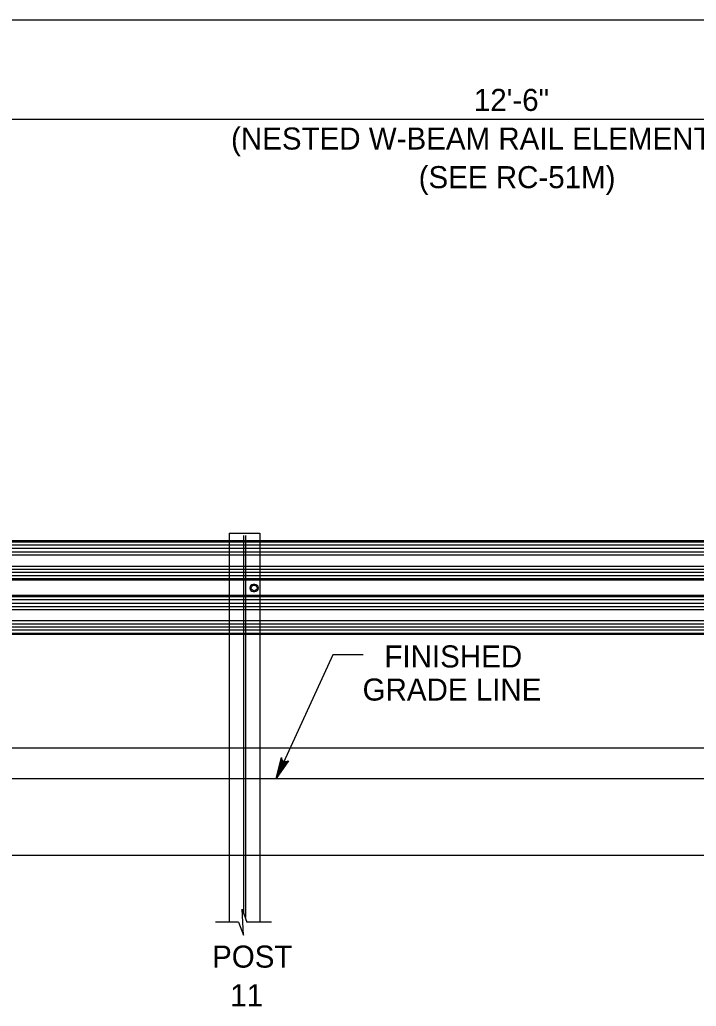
# Model space of a CAD drawing. Extents: x 632007860 to 635435983, y 295418622 to 297794622.
# Drawn here: x 632449960 to 632541897, y 296213999 to 296348078 of the extents above; entities that cross this region are included whole.
import ezdxf

# ---------------------------------------------------------------- set-up
doc = ezdxf.new("R2010")
doc.units = 0
for name, color, linetype in [('S-ABUT', 7, 'Continuous'), ('S-DETL-DIMS', 7, 'Continuous'), ('S-DETL-T120', 7, 'Continuous'), ('S-GRND-MAJR', 7, 'Continuous'), ('S-STEL', 7, 'Continuous')]:
    doc.layers.add(name, color=color, linetype=linetype)

msp = doc.modelspace()

# ---------------------------------------------------------------- linework, layer by layer
at = {"layer": 'S-ABUT'}
for p, q in [((632118834, 296249115), (632656122, 296249115)), ((632141627, 296234532), (632656122, 296234532))]:
    msp.add_line(p, q, dxfattribs=at)
at = {"layer": 'S-DETL-DIMS'}
for p, q in [((632118834, 296348078), (632598995, 296348078)), ((632130592, 296334582), (632596456, 296334582)), ((632492491, 296261755), (632484794, 296244949)), ((632496618, 296261755), (632492491, 296261755)), ((632479670, 296225427), (632476544, 296225427)), ((632484170, 296225427), (632480841, 296225427))]:
    msp.add_line(p, q, dxfattribs=at)
for points in [[(632484794, 296244949), (632485510, 296247824), (632485534, 296247690), (632485558, 296247555), (632485623, 296247462), (632485687, 296247369), (632485769, 296247313), (632485851, 296247257), (632485947, 296247231), (632486043, 296247206), (632486155, 296247218), (632486268, 296247230), (632486386, 296247300), (632486503, 296247369), (632484794, 296244949), (632486386, 296247300), (632486268, 296247230), (632484794, 296244949), (632486155, 296247218), (632486043, 296247206), (632484794, 296244949), (632485947, 296247231), (632485851, 296247257), (632484794, 296244949), (632485769, 296247313), (632485687, 296247369), (632484794, 296244949), (632485623, 296247462), (632485558, 296247555), (632484794, 296244949), (632485534, 296247690)], [(632479670, 296225427), (632480383, 296223669), (632480170, 296227184), (632480841, 296225427)]]:
    msp.add_lwpolyline(points, dxfattribs=at)
at = {"layer": 'S-GRND-MAJR'}
msp.add_line((632118834, 296244949), (632656122, 296244949), dxfattribs=at)
at = {"layer": 'S-STEL'}
for p, q in [((632647109, 296277239), (632437249, 296277239)), ((632647109, 296277070), (632437249, 296277070)), ((632478423, 296278280), (632482591, 296278280)), ((632478423, 296278280), (632478423, 296277238)), ((632478423, 296278280), (632482591, 296278280)), ((632478423, 296278280), (632478423, 296277238)), ((632478423, 296277238), (632478423, 296264508)), ((632480377, 296277997), (632480377, 296226558)), ((632480637, 296277997), (632480637, 296226047)), ((632482591, 296278280), (632482591, 296277238)), ((632482591, 296278280), (632482591, 296277238)), ((632482591, 296277238), (632482591, 296264508)), ((632647109, 296276648), (632437222, 296276648)), ((632647109, 296276648), (632437249, 296276648)), ((632647109, 296276227), (632437249, 296276227)), ((632647389, 296275721), (632437249, 296275721)), ((632647007, 296275299), (632437249, 296275299)), ((632647109, 296273782), (632437249, 296273782)), ((632647109, 296273360), (632437249, 296273360)), ((632647109, 296272939), (632437249, 296272939)), ((632647109, 296272517), (632437249, 296272517)), ((632647109, 296272096), (632437249, 296272096)), ((632647109, 296271927), (632437249, 296271927)), ((632481232, 296270862), (632481232, 296270854)), ((632481232, 296270862), (632481232, 296270854)), ((632481232, 296270845), (632481232, 296270837)), ((632481930, 296271328), (632481697, 296271328)), ((632481930, 296271328), (632481697, 296271328)), ((632481930, 296271310), (632481697, 296271310)), ((632481697, 296270389), (632481930, 296270389)), ((632481697, 296270389), (632481930, 296270389)), ((632481697, 296270371), (632481930, 296270371)), ((632482395, 296270854), (632482395, 296270862)), ((632482395, 296270854), (632482395, 296270862)), ((632482395, 296270837), (632482395, 296270845)), ((632647109, 296269819), (632437249, 296269819)), ((632647109, 296269651), (632437249, 296269651)), ((632647109, 296269229), (632437249, 296269229)), ((632647109, 296268723), (632437249, 296268723)), ((632647454, 296268302), (632437249, 296268302)), ((632647045, 296267880), (632437249, 296267880)), ((632647109, 296266363), (632437249, 296266363)), ((632647109, 296265941), (632437249, 296265941)), ((632647109, 296265520), (632437249, 296265520)), ((632647109, 296265098), (632437249, 296265098)), ((632647109, 296264677), (632437249, 296264677)), ((632647109, 296264508), (632437249, 296264508)), ((632478423, 296264508), (632478423, 296244948)), ((632482591, 296264508), (632482591, 296244948)), ((632478423, 296244948), (632478423, 296225426)), ((632482591, 296244948), (632482591, 296225426))]:
    msp.add_line(p, q, dxfattribs=at)
msp.add_circle((632481813, 296270858), 391, dxfattribs=at)
msp.add_circle((632481813, 296270858), 391, dxfattribs=at)
for centre, start, end in [((632481697, 296270862), 90, 180), ((632481697, 296270862), 90, 180), ((632481697, 296270845), 90, 180), ((632481697, 296270854), 180, 270), ((632481697, 296270854), 180, 270), ((632481697, 296270837), 180, 270), ((632481930, 296270862), 0, 90), ((632481930, 296270862), 0, 90), ((632481930, 296270845), 0, 90), ((632481930, 296270854), 270, 360), ((632481930, 296270854), 270, 360), ((632481930, 296270837), 270, 360)]:
    msp.add_arc(centre, 466, start, end, dxfattribs=at)

# ---------------------------------------------------------------- texts
at = {"layer": 'S-DETL-T120'}
for s, height, p in [(' 12\'-6"', 2999.8, (632510563, 296335681)), ('(NESTED W-BEAM RAIL ELEMENTS)', 2999.85, (632478675, 296330431)), ('(SEE RC-51M)', 2999.85, (632504174, 296325182)), ('FINISHED', 2999.8, (632499516, 296260045)), ('GRADE LINE', 2999.8, (632496551, 296255545)), ('POST', 2999.8, (632476099, 296219248)), ('11', 2999.8, (632478568, 296213999))]:
    msp.add_text(s, height=height, dxfattribs=at).set_placement(p)

doc.saveas('drawing.dxf')
